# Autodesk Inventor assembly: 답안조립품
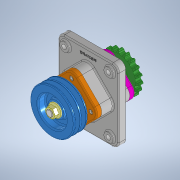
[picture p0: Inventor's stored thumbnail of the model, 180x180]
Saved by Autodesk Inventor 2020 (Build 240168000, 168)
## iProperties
Created: 2021-07
Part Number: 답안조립품
Document SubType Name: Assembly
Designer: Owner
Author: Owner
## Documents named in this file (16)
- C:\Users\Owner\Desktop\710707V1018\710707V1018\답안조립품.iam
- C:\Users\Owner\Desktop\710707V1018\710707V1018\본체.ipt
- C:\Users\Owner\Desktop\710707V1018\710707V1018\M16 너트.ipt
- C:\Users\Owner\Desktop\710707V1018\710707V1018\V-벨트풀리.ipt
- C:\Users\Owner\Desktop\710707V1018\710707V1018\멈춤나사 M4.ipt
- C:\Users\Owner\Desktop\710707V1018\710707V1018\베어링 6206.ipt
- C:\Users\Owner\Desktop\710707V1018\710707V1018\볼트 M6.ipt
- C:\Users\Owner\Desktop\710707V1018\710707V1018\오일실 30x42x8.ipt
- C:\Users\Owner\Desktop\710707V1018\710707V1018\오일실 30x45x8.ipt
- C:\Users\Owner\Desktop\710707V1018\710707V1018\체인 스프로킷.ipt
- C:\Users\Owner\Desktop\710707V1018\710707V1018\축.ipt
- C:\Users\Owner\Desktop\710707V1018\710707V1018\커버A.ipt
- C:\Users\Owner\Desktop\710707V1018\710707V1018\커버B.ipt
- C:\Users\Owner\Desktop\710707V1018\710707V1018\키 6x6x18.ipt
- C:\Users\Owner\Desktop\710707V1018\710707V1018\키 6x6x20.ipt
- C:\Users\Owner\Desktop\710707V1018\710707V1018\부시.ipt
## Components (3 placed, 2 different names)
1. M16 너트:1
2. V-벨트풀리:1 — 각도:2
3. M16 너트:2
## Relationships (1: Angle 1)
- 각도:2 [Angle]: V-벨트풀리:1
